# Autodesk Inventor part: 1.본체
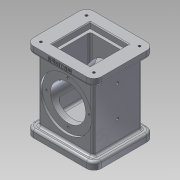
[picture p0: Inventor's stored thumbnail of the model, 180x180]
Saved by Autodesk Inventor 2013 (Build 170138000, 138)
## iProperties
Created: 2017-08
Part Number: 1.본체
Material: 알루미늄 6061
Document SubType Name: Modeling
Designer: cad14
Density: 2.40731 g/cm^3
Mass: 774.891 g
Surface Area: 642.254 cm^2
Volume: 321.891 cm^3
Author: cad14
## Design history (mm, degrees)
sketch "스케치1"
  geometry: L1 (-46, -41)-(46, -41); L2 (46, -41)-(46, 41); L3 (46, 41)-(-46, 41); L4 (-46, 41)-(-46, -41); L5 (-46, -41)-(46, 41); L6 (46, -41)-(-46, 41); 1 further point
  constraints: 12 end point, 2 midpoint, 2 parallel, 1 horizontal, 1 perpendicular
  dimensions: "d0" = 92 distance between parallel lines of L2 L4; "d2" = 82 distance between parallel lines of L3 L1
extrude "돌출1" new body sketch "스케치1" distance "d3" = 10; taper "d4" = 0 deg
sketch "스케치2"
  geometry: L1 (-37, -33)-(37, -33); L2 (37, -33)-(37, 33); L3 (37, 33)-(-37, 33); L4 (-37, 33)-(-37, -33); L5 (-37, -33)-(37, 33); L6 (37, -33)-(-37, 33); 1 further point
  constraints: 12 end point, 2 midpoint, 2 parallel, 1 horizontal, 1 perpendicular
  dimensions: "d5" = 74 distance between parallel lines of L2 L4; "d7" = 66 distance between parallel lines of L3 L1
extrude "돌출2" join sketch "스케치2" distance "d8" = 88; taper "d9" = 0 deg
sketch "스케치3"
  geometry: L1 (-46, -41)-(46, -41); L2 (46, -41)-(46, 41); L3 (46, 41)-(-46, 41); L4 (-46, 41)-(-46, -41); L5 (-46, -41)-(46, 41); L6 (46, -41)-(-46, 41); 1 further point
  constraints: 12 end point, 2 midpoint, 2 parallel, 1 horizontal, 1 perpendicular
  dimensions: "d10" = 92 distance between parallel lines of L2 L4; "d12" = 82 distance between parallel lines of L3 L1
extrude "돌출3" join sketch "스케치3" distance "d13" = 10; taper "d14" = 0 deg
sketch "스케치4"
  geometry: L1 (-22, -22)-(22, -22); L2 (22, -22)-(22, 22); L3 (22, 22)-(-22, 22); L4 (-22, 22)-(-22, -22); L5 (-22, -22)-(22, 22); L6 (22, -22)-(-22, 22); 1 further point
  constraints: 12 end point, 2 midpoint, 2 parallel, 1 horizontal, 1 perpendicular
  dimensions: "d15" = 44 distance between parallel lines of L2 L4; "d17" = 44 distance between parallel lines of L1 L3
extrude "돌출4" cut sketch "스케치4" distance "d18" = 82; taper "d19" = 0 deg
sketch "스케치5"
  geometry: L1 (22, 22)-(22, -22) reference; L2 (22, -22)-(-22, -22) reference; L3 (-22, -22)-(-22, 22) reference; L4 (-22, 22)-(22, 22) reference; L5 (-26, -26)-(26, -26); L6 (26, -26)-(26, 26); L7 (26, 26)-(-26, 26); L8 (-26, 26)-(-26, -26); L9 (-26, -26)-(26, 26); L10 (26, -26)-(-26, 26); 1 further point
  constraints: 12 end point, 2 midpoint, 2 parallel, 1 horizontal, 1 perpendicular
  dimensions: "d20" = 52 distance between parallel lines of L6 L8; "d22" = 52 distance between parallel lines of L7 L5
extrude "돌출5" cut sketch "스케치5" distance "d23" = 8; taper "d24" = 0 deg
sketch "스케치6"
  geometry: L1 (-9, -10)-(83, -10) reference; C1 r 24 at (37, 44); 2 further points
  constraints: 1 centre point, 1 midpoint, 1 vertical alignment
  dimensions: "d25" = 54 distance from line of C1.centre L1; "d26" = 48 diameter of C1
extrude "돌출6" cut sketch "스케치6" stored distance "d27" = 8; taper "d28" = 0 deg
sketch "스케치7"
  geometry: C1 r 24 at (37, 44) reference; C2 r 35 at (37, 44); 1 further point
  constraints: 1 centre point
  dimensions: "d29" = 70 diameter of C2
extrude "돌출7" cut sketch "스케치7" distance "d31" = 3; taper "d32" = 0 deg
sketch "스케치8"
  geometry: L1 (-24, -24)-(24, -24); L2 (24, -24)-(24, 24); L3 (24, 24)-(-24, 24); L4 (-24, 24)-(-24, -24); L5 (-24, -24)-(24, 24); L6 (24, -24)-(-24, 24); 1 further point
  constraints: 12 end point, 2 midpoint, 2 parallel, 1 horizontal, 1 perpendicular
  dimensions: "d33" = 48 distance between parallel lines of L2 L4; "d35" = 48 distance between parallel lines of L3 L1
extrude "돌출8" cut sketch "스케치8" distance "d36" = 16; taper "d37" = 0 deg
sketch "스케치9"
  geometry: C1 r 24 at (0, 0) reference; 2 further points
  constraints: 1 vertical alignment
  dimensions: "d38" = 29 distance of point (0, 29) C1.centre
hole "구멍1" sketch "스케치9" at (0, 29) diameter "d39" = 3.242; stored, may be unused: countersink angle "d43" = 90 deg, drill point angle "d45" = 118 deg; dims "d40" = 4, "d41" = 4, "d42" = 2, "d44" = 6
sketch "스케치10"
  geometry: L1 (10, -8)-(10, 74) reference; 5 further points
  constraints: 2 horizontal alignment, 2 midpoint
  dimensions: "d49" = 38 distance from line of point (-28, 33) L1; "d50" = 42 distance of point (-70, 33) point (-28, 33)
hole "구멍2" sketch "스케치10" at (-28, 33), (-70, 33) diameter "d51" = 4.134; stored, may be unused: countersink angle "d55" = 90 deg, drill point angle "d57" = 118 deg; dims "d52" = 4, "d53" = 4, "d54" = 2, "d56" = 20
fillet "모깎기1" dims "d58" = 10
fillet "모깎기2" dims "d59" = 3
fillet "모깎기3" dims "d60" = 3
fillet "모깎기5" dims "d62" = 3
fillet "모깎기6" dims "d63" = 3
sketch "스케치11"
  geometry: A1 r 10 centre (-36, 31) between (-36, 41) and (-46, 31) reference; A2 r 10 centre (-36, -31) between (-46, -31) and (-36, -41) reference; A3 r 10 centre (36, -31) between (36, -41) and (46, -31) reference; A4 r 10 centre (36, 31) between (46, 31) and (36, 41) reference; 1 further point
hole "구멍3" sketch "스케치11" at (-36, 31), (36, 31), (36, -31), (-36, -31) diameter "d64" = 3.242; stored, may be unused: countersink angle "d68" = 90 deg, drill point angle "d70" = 118 deg; dims "d65" = 4, "d66" = 4, "d67" = 2, "d69" = 6
sketch "스케치12"
  geometry: A1 r 10 centre (36, 31) between (46, 31) and (36, 41) reference; A2 r 10 centre (-36, 31) between (-36, 41) and (-46, 31) reference; A3 r 10 centre (-36, -31) between (-46, -31) and (-36, -41) reference; A4 r 10 centre (36, -31) between (36, -41) and (46, -31) reference; 1 further point
hole "구멍4" sketch "스케치12" at (-36, 31), (-36, -31), (36, -31), (36, 31) diameter "d71" = 3.242; stored, may be unused: countersink angle "d75" = 90 deg, drill point angle "d77" = 118 deg; dims "d72" = 4, "d73" = 4, "d74" = 2, "d76" = 6
fillet "모깎기7" dims "d78" = 3
fillet "모깎기8" dims "d79" = 3
fillet "모깎기9" dims "d80" = 3
node "작업 평면2"
sketch "스케치14"
  geometry: L1 (-10, 0)-(-10, -7) reference; L2 (0, 0)-(72, 0) reference; 2 further points
  constraints: 1 other
  dimensions: "d87" = 46 distance from line of point (36, -4) L1; "d88" = 4 distance from line of point (36, -4) L2
feature "엠보싱2" sketch "스케치14" dims "d0" = 92, "d2" = 82, "d89" = 0.5, "d90" = 0
chamfer "모따기1" distance "d91" = 1; stored, may be unused: second distance "d92" = 2, angle "d93" = 45 deg
node "솔리드1"
mirror "대칭1"
pattern_circular "원형 패턴1" dims angle "d47" = 360 deg
mirror "대칭2"
